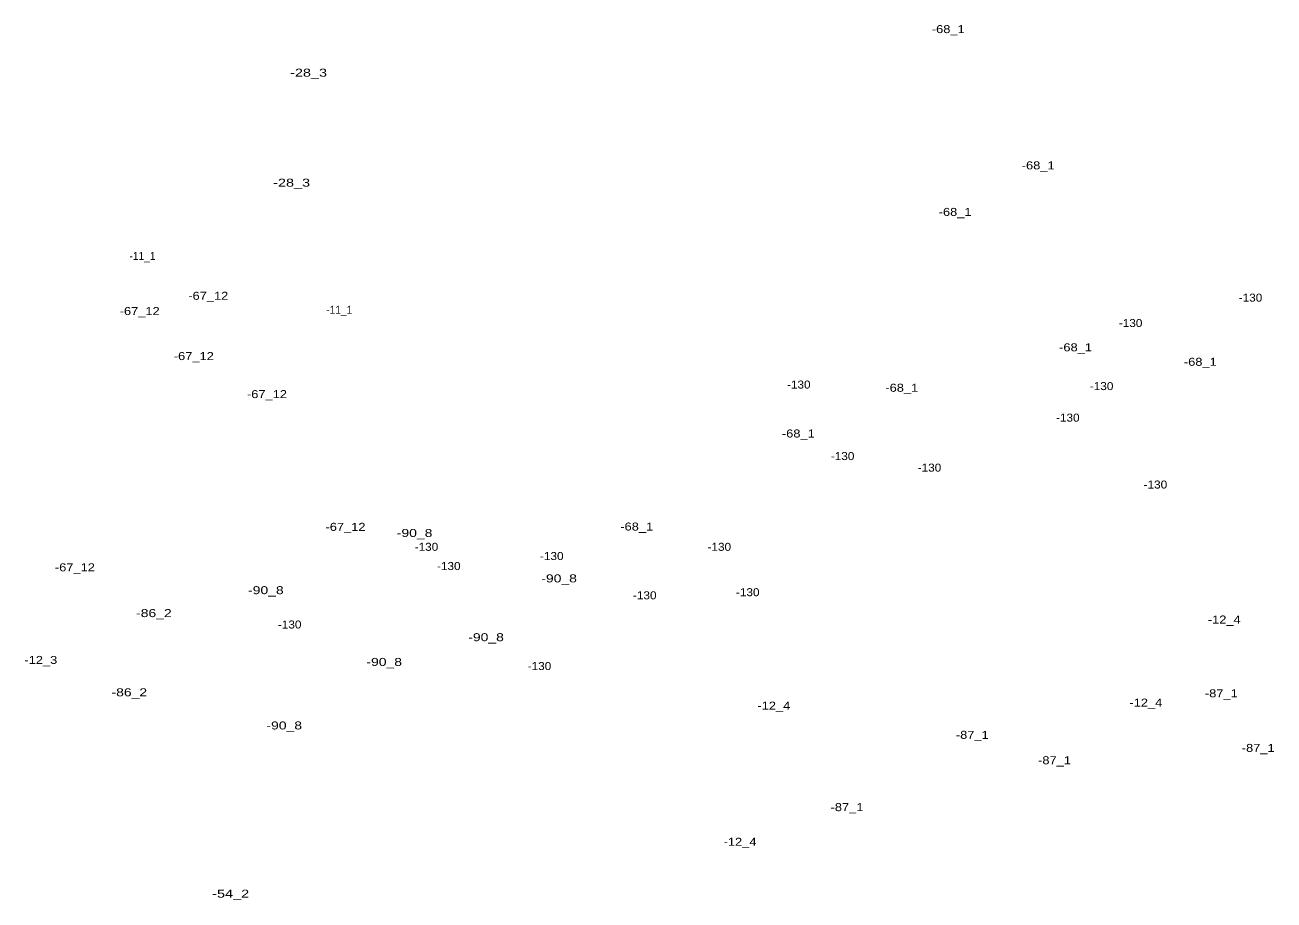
# Model space of a CAD drawing. Extents: x -662996 to -659766, y -998554 to -993949.
# Drawn here: x -662463 to -661839, y -996264 to -995827 of the extents above; entities that cross this region are included whole.
import ezdxf
from ezdxf.enums import TextEntityAlignment as Align

# ---------------------------------------------------------------- set-up
doc = ezdxf.new("R2010")
doc.units = 0
doc.header["$LTSCALE"] = 1.6
doc.layers.add('24', color=7, linetype='Continuous')

msp = doc.modelspace()

# ---------------------------------------------------------------- texts
at = {"layer": '24'}
for s, width, p in [('-68_1', 1.2, (-662001.961, -995831.12)), ('-28_3', 1.35, (-662321.579, -995852.89)), ('-68_1', 1.2, (-661957.03, -995899.18)), ('-28_3', 1.35, (-662330.03, -995907.82)), ('-68_1', 1.2, (-661998.541, -995922.42)), ('-11_1', 0.95, (-662404.53, -995944.42)), ('-67_12', 1.2, (-662371.67, -995964.32)), ('-130', 1.1, (-661850.961, -995965.24)), ('-67_12', 1.2, (-662405.94, -995971.94)), ('-11_1', 0.95, (-662306.22, -995971.31)), ('-130', 1.1, (-661910.861, -995977.92)), ('-67_12', 1.2, (-662378.9, -995994.42)), ('-68_1', 1.2, (-661938.37, -995990.06)), ('-68_1', 1.2, (-661876.03, -995997.29)), ('-67_12', 1.2, (-662342.35, -996013.43)), ('-130', 1.1, (-662076.64, -996008.65)), ('-68_1', 1.2, (-662025.191, -996010.25)), ('-130', 1.1, (-661925.341, -996009.42)), ('-130', 1.1, (-661942.24, -996025.17)), ('-68_1', 1.2, (-662076.87, -996033.1)), ('-130', 1.1, (-662054.75, -996044.37)), ('-130', 1.1, (-662011.361, -996050.14)), ('-130', 1.1, (-661898.461, -996058.59)), ('-67_12', 1.2, (-662303.12, -996079.72)), ('-90_8', 1.3, (-662268.59, -996082.78)), ('-68_1', 1.2, (-662157.601, -996079.58)), ('-130', 1.1, (-662262.66, -996089.7)), ('-130', 1.1, (-662200.061, -996094.31)), ('-130', 1.1, (-662116.351, -996089.7)), ('-67_12', 1.2, (-662438.31, -996099.94)), ('-130', 1.1, (-662251.52, -996099.31)), ('-90_8', 1.3, (-662196.4, -996105.47)), ('-90_8', 1.3, (-662342.9, -996111.36)), ('-130', 1.1, (-662153.601, -996113.91)), ('-130', 1.1, (-662102.14, -996112.37)), ('-86_2', 1.3, (-662398.84, -996122.8)), ('-12_4', 1.2, (-661864.069, -996126.01)), ('-130', 1.1, (-662331.01, -996128.5)), ('-90_8', 1.3, (-662232.89, -996134.84)), ('-12_3', 1.2, (-662455.329, -996146.2)), ('-90_8', 1.3, (-662283.78, -996147.19)), ('-130', 1.1, (-662206.211, -996149.25)), ('-86_2', 1.3, (-662411.13, -996162.36)), ('-87_1', 1.2, (-661865.53, -996162.87)), ('-12_4', 1.2, (-662089.1, -996169.04)), ('-12_4', 1.2, (-661903.24, -996167.5)), ('-90_8', 1.3, (-662333.72, -996178.92)), ('-87_1', 1.2, (-661989.95, -996183.61)), ('-87_1', 1.2, (-661847.1, -996190.14)), ('-87_1', 1.2, (-661948.87, -996196.29)), ('-87_1', 1.2, (-662052.55, -996219.72)), ('-12_4', 1.2, (-662106, -996237.03)), ('-54_2', 1.35, (-662360.49, -996262.95))]:
    msp.add_text(s, height=4, dxfattribs=dict(at, width=width)).set_placement(p, align=Align.CENTER)

doc.saveas('drawing.dxf')
